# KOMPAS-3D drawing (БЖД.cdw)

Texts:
  ДП.11.213.07.000.00.ТБ
  СПК колхоз "Дзержинского" Даниловского МР Ярославской обл.
  Показатели
  Годы
  Среднесписочная численность
  работников
  Число пострадавших с утратой
  трудоспособности на 1 день и более
  Число несчастных случаев со
  смертельным исходом
  Число дней нетрудоспособности
  из-за травматизма
  Коэффициент частоты произ-
  водственного травматизма, Кч
  - по хозяйству
  - по области
  Коэффициент тяжести произ-
  водственного травматизма, Кт
  Коэффициент потерь рабочего
  времени, Кп
  Затраты на мероприятия по
  охране труда, руб./чел
  СПК колхоз "Дзержинского"
  Даниловского МР Ярославской обл.
  Разраб.
  Куракин
  Пров.
  Шмигель
  Королёва
  Утв.
  Орлов
  ФГОУ ВПО ЯГСХА
  ДП.09.511.07Д3-
  Основные показатели работы
  по охране труда
  Юрков
Dimensions and other numbers on the sheet: 2004; 2005; 2006; 2007; 2008; 2009; 2010; 1; 177; 163; 104; 115; 89; 81; 2; 3; 4; 5; 12,7; 7,4; 6,5; 5,4; 5,6; 5,2; 3,6; 6; 23,5; 30,2; 33,0; 25,4; 33,5; 35,5; 42,0; 7; 298,0; 223,0; 214,0; 137,2; 187,6; 184,6; 151,2; 8; 147,0; 204,3; 365,4; 347,8; 495,0; 640,5; 1402,3; 195,0; 284,0; 411,0; 447,0; 568,0; 543,7; 1517,6; 0; 9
